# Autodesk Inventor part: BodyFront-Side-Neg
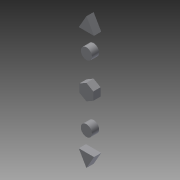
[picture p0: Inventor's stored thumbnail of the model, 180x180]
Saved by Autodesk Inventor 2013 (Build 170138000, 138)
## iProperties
Created: 2013-04
Part Number: BodyFront-Side-Neg
Material: Generic
Document SubType Name: Modeling
Designer: frankenteddy
Density: 1 g/cm^3
Author: frankenteddy
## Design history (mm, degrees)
sketch "Sketch1"
  geometry: L1 (-6.86, 1.3)-(-0.14, 1.3); L2 (-0.14, 1.3)-(-6.86, 1.3); L3 (-0.14, 63.7)-(-0.14, 1.3); L4 (-0.14, 63.7)-(-0.14, 1.3); L5 (-6.86, 1.3)-(-6.86, 63.7); L6 (-6.86, 1.3)-(-6.86, 63.7); L7 (-6.86, 44.02)-(-0.14, 44.02); L8 (-6.86, 52.18)-(-0.14, 52.18); L9 (-6.14, 50.656)-(-3.5, 55.228); L10 (-3.5, 55.228)-(-0.86, 50.656); L11 (-0.86, 50.656)-(-6.14, 50.656); L12 (-6.86, 63.7)-(-0.14, 63.7); L13 (-6.86, 63.7)-(-0.14, 63.7); L14 (-6.86, 20.98)-(-0.14, 20.98); L15 (-6.14, 14.344)-(-0.86, 14.344); L16 (-6.86, 12.82)-(-0.14, 12.82); L17 (-3.5, 9.772)-(-6.14, 14.344); L18 (-0.86, 14.344)-(-3.5, 9.772); L19 (-3.5, 35.275)-(-1.096, 33.888); L20 (-5.904, 33.888)-(-3.5, 35.275); L21 (-6.86, 32.5)-(-0.14, 32.5); L22 (-5.904, 31.112)-(-5.904, 33.888); L23 (-3.5, 29.725)-(-5.904, 31.112); L24 (-1.096, 31.112)-(-3.5, 29.725); L25 (-1.096, 33.888)-(-1.096, 31.112); C1 r 1.92 at (-3.5, 44.02); C2 r 1.92 at (-3.5, 20.98); 5 further points
  constraints: 50 end point, 8 point on line, 7 midpoint, 4 parallel, 3 perpendicular, 2 centre point, 1 horizontal, 27 other
  dimensions: "d0" = 6.72 distance of L1.end L2.end (derived); "d1" = 62.4 distance of L4.start L1.end (derived); "d2" = 11.52 distance between parallel lines of L8 L13; "d3" = 11.52 distance between parallel lines of L16 L1; "d4" = 11.52 distance between parallel lines of L14 L21; "d5" = 11.52 distance between parallel lines of L7 L21; "d6" = 5.28 distance of L10.end L9.start; "d7" = 5.28 distance of L15.start L15.end; "d8" = 3.84 diameter of C1; "d9" = 3.84 diameter of C2
extrude "Extrusion1" new body sketch "Sketch1" distance "d10" = 2.5; taper "d11" = 0 deg
body "Solid1"
